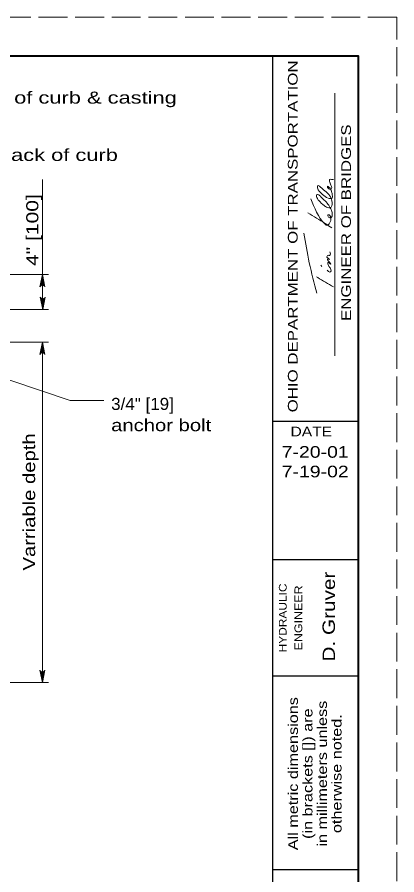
# Model space of a CAD drawing. Extents: x 1352.5 to 1386.5, y 735.9 to 779.9.
# Drawn here: x 1381.62 to 1386.51, y 768.86 to 779.92 of the extents above; entities that cross this region are included whole.
import ezdxf
from ezdxf.enums import TextEntityAlignment as Align

# ---------------------------------------------------------------- set-up
doc = ezdxf.new("R2010")
doc.units = 0
doc.header["$LTSCALE"] = 0.062
doc.linetypes.add('LONG_DASHED', pattern=[7.5, 6, -1.5])
doc.layers.add('1', color=7, linetype='Continuous', lineweight=13)

msp = doc.modelspace()

# ---------------------------------------------------------------- linework, layer by layer
at = {"layer": '1', "lineweight": 25}
for p, q in [((1354.513, 779.41967), (1386.013, 779.41967)), ((1384.913, 758.41967), (1384.913, 779.41967)), ((1386.013, 779.41967), (1386.013, 758.41967)), ((1386.013, 774.70383), (1384.913, 774.70383)), ((1386.013, 772.91967), (1384.913, 772.91967)), ((1386.013, 771.41967), (1384.913, 771.41967)), ((1386.013, 768.91967), (1384.913, 768.91967))]:
    msp.add_line(p, q, dxfattribs=at)
at = {"layer": '1'}
for p, q in [((1385.71175, 775.55067), (1385.71175, 778.94075)), ((1381.94175, 776.14925), (1381.94175, 777.8275)), ((1385.54425, 776.70158), (1385.53408, 776.72083)), ((1379.54517, 776.599), (1382.02042, 776.599)), ((1381.9195, 776.45308), (1381.94175, 776.599)), ((1381.92883, 776.45858), (1381.94175, 776.599)), ((1381.94175, 776.46117), (1381.94175, 776.599)), ((1381.952, 776.45967), (1381.94175, 776.599)), ((1381.962, 776.45475), (1381.94175, 776.599)), ((1381.92633, 776.2935), (1381.9465, 776.14925)), ((1381.93633, 776.28858), (1381.9465, 776.14925)), ((1381.96883, 776.29517), (1381.9465, 776.14925)), ((1381.9595, 776.28967), (1381.9465, 776.14925)), ((1381.9465, 776.28708), (1381.9465, 776.14925)), ((1381.10383, 776.14925), (1382.02042, 776.14925)), ((1378.38592, 775.72767), (1382.02042, 775.72767)), ((1381.9195, 775.58175), (1381.94175, 775.72767)), ((1381.92883, 775.58733), (1381.94175, 775.72767)), ((1381.94175, 775.58983), (1381.94175, 775.72767)), ((1381.952, 775.58833), (1381.94175, 775.72767)), ((1381.962, 775.5835), (1381.94175, 775.72767)), ((1381.94175, 771.337), (1381.94175, 775.72767)), ((1381.92158, 771.48125), (1381.94175, 771.337)), ((1381.93158, 771.47633), (1381.94175, 771.337)), ((1381.96408, 771.48292), (1381.94175, 771.337)), ((1381.95475, 771.47742), (1381.94175, 771.337)), ((1381.94175, 771.47492), (1381.94175, 771.337)), ((1380.49558, 771.337), (1382.02108, 771.337))]:
    msp.add_line(p, q, dxfattribs=at)
at = {"layer": '1', "linetype": 'LONG_DASHED'}
msp.add_lwpolyline([(1352.513, 757.91967), (1386.513, 757.91967), (1386.513, 779.91967), (1352.513, 779.91967)], close=True, dxfattribs=at)
at = {"layer": '1', "lineweight": 40}
msp.add_lwpolyline([(1354.513, 779.41967), (1386.013, 779.41967), (1386.013, 758.41967), (1354.513, 758.41967)], close=True, dxfattribs=at)
msp.add_lwpolyline([(1354.513, 779.41967), (1386.013, 779.41967), (1386.013, 758.41967), (1354.513, 758.41967)], close=True, dxfattribs=at)
at = {"layer": '1'}
for points in [[(1381.90992, 776.43975), (1381.94175, 776.599), (1381.97367, 776.43975)], [(1381.97842, 776.30858), (1381.9465, 776.14925), (1381.91467, 776.30858)], [(1379.593, 775.88575), (1382.298, 774.97567), (1382.73225, 774.97567)], [(1381.90992, 775.56842), (1381.94175, 775.72767), (1381.97367, 775.56842)], [(1381.97367, 771.49633), (1381.94175, 771.337), (1381.90992, 771.49633)]]:
    msp.add_lwpolyline(points, dxfattribs=at)
for centre, start, end in [((1381.94183, 776.42684), 22.08782, 157.91395), ((1381.9465, 776.32143), 202.08782, 337.91395), ((1381.94182, 775.55554), 22.08782, 157.91395), ((1381.94175, 771.5092), 202.08782, 337.91395)]:
    msp.add_arc(centre, 0.03438, start, end, dxfattribs=at)
for points in [[(1385.40483, 777.57667), (1385.588, 777.24833), (1385.60317, 777.23775), (1385.61333, 777.23775), (1385.64525, 777.26142), (1385.66033, 777.29558), (1385.65533, 777.34683), (1385.63842, 777.36867), (1385.62492, 777.36867), (1385.62317, 777.35567), (1385.63333, 777.3405), (1385.64683, 777.33208), (1385.66192, 777.33208), (1385.67708, 777.35367), (1385.6805, 777.373), (1385.67025, 777.42833), (1385.588, 777.54875), (1385.5425, 777.59342), (1385.50558, 777.628), (1385.48042, 777.63017), (1385.48217, 777.59158), (1385.50733, 777.55283), (1385.57458, 777.4905), (1385.61667, 777.46508), (1385.65033, 777.46058), (1385.67367, 777.48658), (1385.6805, 777.52075), (1385.67542, 777.5465), (1385.64525, 777.61967), (1385.615, 777.65167), (1385.55442, 777.70508), (1385.52575, 777.73092), (1385.49225, 777.74617), (1385.48883, 777.71817), (1385.49892, 777.69233), (1385.55608, 777.63242), (1385.62675, 777.58517), (1385.67875, 777.5875), (1385.67708, 777.64517), (1385.66525, 777.68808), (1385.65192, 777.71383), (1385.64175, 777.72458), (1385.61833, 777.73958), (1385.62008, 777.7225), (1385.65533, 777.701), (1385.67025, 777.71175), (1385.65717, 777.76542), (1385.64858, 777.79333), (1385.64525, 777.806), (1385.64525, 777.81883), (1385.64525, 777.8275), (1385.67025, 777.82533), (1385.69567, 777.82533)], [(1385.366, 777.39442), (1385.58975, 777.25692), (1385.67542, 777.20125)], [(1385.48225, 776.35742), (1385.38358, 776.75267), (1385.31233, 777.135)], [(1385.61333, 776.65633), (1385.62158, 776.64567), (1385.65875, 776.63275), (1385.6635, 776.66517), (1385.63842, 776.70158), (1385.62317, 776.73783), (1385.62317, 776.75708), (1385.63842, 776.75083), (1385.64858, 776.74), (1385.65875, 776.73567), (1385.63508, 776.76783), (1385.62317, 776.78283), (1385.62008, 776.80017), (1385.6435, 776.79358), (1385.63508, 776.80225), (1385.60992, 776.83008), (1385.62008, 776.84525), (1385.63683, 776.84725), (1385.64525, 776.84525), (1385.65533, 776.86658), (1385.64858, 776.8945)], [(1385.69742, 776.44183), (1385.49225, 776.56183), (1385.47667, 776.57225)]]:
    msp.add_spline(points, degree=3, dxfattribs=at)

# ---------------------------------------------------------------- texts
for s, height, width, p in [('OHIO DEPARTMENT OF TRANSPORTATION', 0.125, 1.3, (1385.23292, 777.09192)), ('ENGINEER OF BRIDGES', 0.125, 1.3, (1385.92125, 777.26871)), ('Varriable depth', 0.156, 1.25, (1381.84842, 773.66671)), ('D. Gruver', 0.16, 1.25, (1385.715, 772.18792)), ('HYDRAULIC', 0.1, 1.15, (1385.09208, 772.17075)), ('ENGINEER', 0.1, 1.2, (1385.293, 772.17079)), ('All metric dimensions', 0.125, 1.25, (1385.23683, 770.16175)), ('in millimeters unless', 0.125, 1.25, (1385.61183, 770.16179)), ('(in brackets []) are', 0.125, 1.25, (1385.42433, 770.16175)), ('otherwise noted.', 0.125, 1.25, (1385.79933, 770.16175))]:
    msp.add_text(s, height=height, rotation=90, dxfattribs=dict(at, width=width)).set_placement(p, align=Align.CENTER)
for s, width, p in [('Top of curb & casting', 1.35, (1381.01417, 778.80442)), ('Back of curb', 1.35, (1381.35008, 778.06483)), ('3/4" [19]', 1.05, (1382.82858, 774.853)), ('anchor bolt', 1.25, (1382.82858, 774.579))]:
    msp.add_text(s, height=0.156, dxfattribs=dict(at, width=width)).set_placement(p)
at = {"layer": '1', "width": 1.3}
msp.add_text('4" [100]', height=0.156, rotation=90, dxfattribs=at).set_placement((1381.88958, 776.71033))
at = {"layer": '1'}
for s, height, width, p in [('DATE', 0.125, 1.2, (1385.40971, 774.51242)), ('7-20-01', 0.15, 1.25, (1385.46004, 774.23692)), ('7-19-02', 0.15, 1.25, (1385.46004, 773.98383))]:
    msp.add_text(s, height=height, dxfattribs=dict(at, width=width)).set_placement(p, align=Align.CENTER)

doc.saveas('drawing.dxf')
